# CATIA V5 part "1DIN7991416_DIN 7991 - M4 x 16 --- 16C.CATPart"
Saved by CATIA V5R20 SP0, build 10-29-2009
Part number: 1DIN7991416_DIN 7991 - M4 x 16 --- 16C
Revision: ANY
Definition: UNKNOWN
Nomenclature: 1DIN7991416_DIN 7991 - M4 x 16 --- 16C
Source: Unknown
Bounding box of the stored display mesh (mm): x 0 to 16, y -3.633 to 3.633, z -3.82 to 3.82
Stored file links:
  C:\Users\Utente\Desktop\IO LAVORO\3D X SITO CF\CUMSA\3D files PW\pw060830\pw060830_ejection\1DIN7991416_DIN 7991 - M4 x 16 --- 16C.CATPart
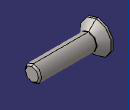
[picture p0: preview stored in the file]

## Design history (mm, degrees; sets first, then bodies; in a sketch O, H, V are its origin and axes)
Body1 "Hex" (main body)
  Solid1: solid without history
